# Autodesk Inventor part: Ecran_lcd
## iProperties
Created: 2011-01
Part Number: Ecran_lcd
Document SubType Name: Modeling
Designer: eric
Density: 1 g/cm^3
Mass: 14.2711 g
Surface Area: 55.7149 cm^2
Volume: 14.2711 cm^3
Author: eric
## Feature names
1. Base1
